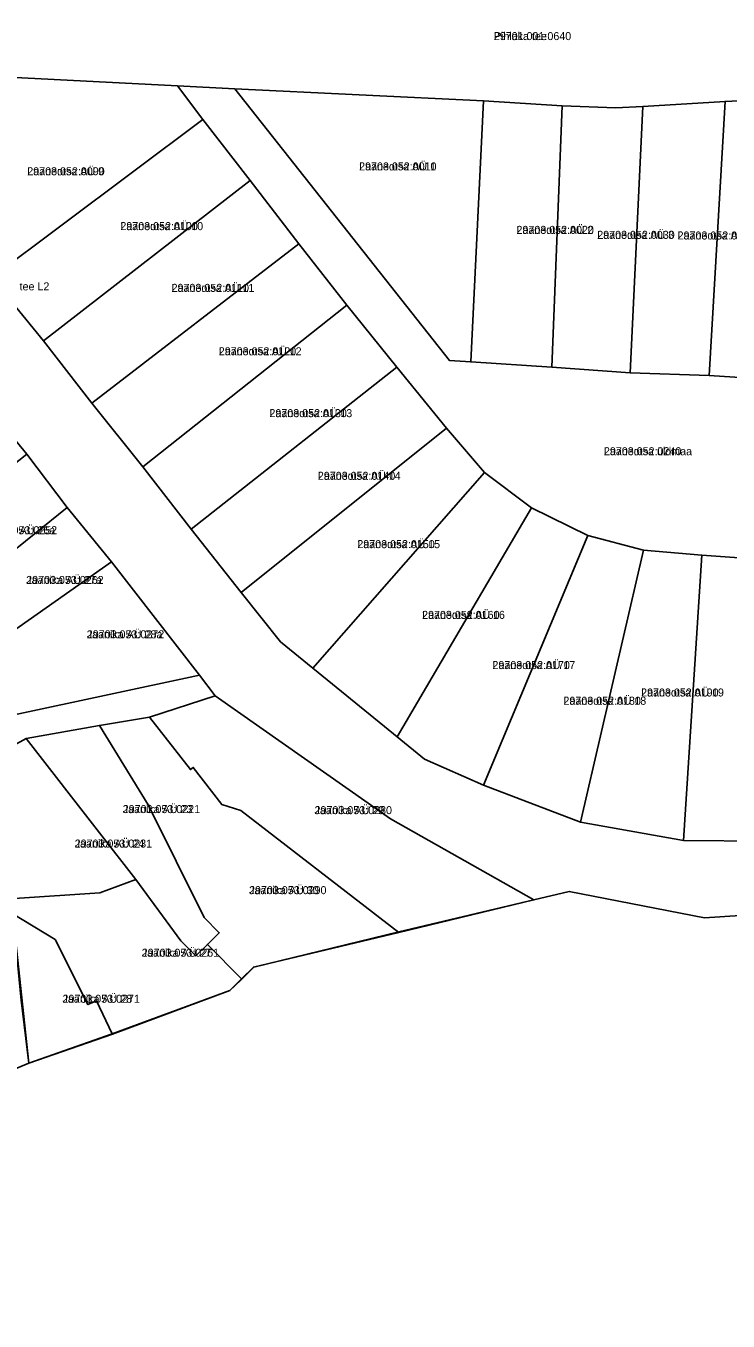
# Model space of a CAD drawing. Extents: x 504287 to 537970, y 6539941 to 6586214.
# Drawn here: x 520134.2 to 520265.8, y 6560331.5 to 6560574.3 of the extents above; entities that cross this region are included whole.
import ezdxf

# ---------------------------------------------------------------- set-up
doc = ezdxf.new("R2010")
doc.units = 0
for name, color, linetype in [('L_AADRESS', 7, 'Continuous'), ('PIIR', 7, 'Continuous'), ('TUNNUS', 7, 'Continuous')]:
    doc.layers.add(name, color=color, linetype=linetype)

msp = doc.modelspace()

# ---------------------------------------------------------------- linework, layer by layer
at = {"layer": 'PIIR'}
for points in [[(520317.67, 6560410.76), (520261.34, 6560407.08), (520236.03, 6560412.01), (520229.4, 6560410.43), (520202.53, 6560425.6), (520169.69, 6560448.66), (520166.73, 6560452.57), (520150.28, 6560473.8), (520141.99, 6560483.98), (520134.38, 6560493.96), (520126.38, 6560503.73), (520118.31, 6560513.94), (520110.33, 6560523.99), (520102.51, 6560533.91), (520094.46, 6560543.92), (520086.59, 6560553.88), (520078.34, 6560564.2), (520070.55, 6560574.23), (520062.55, 6560584.16)], [(520116.2, 6560584.35), (520116.35, 6560565.44), (520115.48, 6560542.75), (520127.8, 6560527.12), (520137.54, 6560515.21), (520146.56, 6560503.53), (520156.13, 6560491.62), (520165.22, 6560479.92), (520174.59, 6560468.07), (520181.93, 6560458.8), (520187.96, 6560453.84), (520203.1, 6560441.57), (520208.92, 6560436.83), (520219.98, 6560431.92), (520238.13, 6560424.99), (520257.44, 6560421.57), (520272.57, 6560421.42)], [(519883.63, 6560513.22), (519926.01, 6560463.67), (519941.07, 6560442.67), (519946.42, 6560436.64), (519971.42, 6560403.04), (519983.27, 6560387.35), (520001.63, 6560363.05), (520022.7, 6560331.46), (520067.9, 6560359.45), (520095.31, 6560364.72), (520109.58, 6560369.9), (520131.77, 6560378.57), (520134.78, 6560379.84), (520150.44, 6560385.26), (520172.45, 6560393.42), (520174.51, 6560395.38), (520176.91, 6560397.82), (520204.12, 6560404.43), (520229.4, 6560410.43), (520236.03, 6560412.01), (520261.34, 6560407.08), (520317.67, 6560410.76)], [(520132.03, 6560445.14), (520166.73, 6560452.57), (520169.69, 6560448.66), (520157.39, 6560444.7), (520148, 6560443.15), (520134.29, 6560440.71), (520131.93, 6560439.39)], [(520131.78, 6560407.84), (520134.78, 6560379.84), (520131.77, 6560378.57)]]:
    msp.add_lwpolyline(points, dxfattribs=at)
for points in [[(520116.2, 6560584.35), (520143.89, 6560583.03), (520172.86, 6560581.52), (520203.54, 6560580.07), (520236.32, 6560578.42), (520254.12, 6560578.76), (520255.84, 6560578.81), (520274.81, 6560579.95), (520296.22, 6560581), (520324.82, 6560582.86), (520329.36, 6560563.63), (520310.39, 6560562.71), (520295.35, 6560561.83), (520280.17, 6560560.87), (520265.21, 6560560.11), (520249.8, 6560559.14), (520244.74, 6560558.9), (520234.71, 6560559.27), (520219.94, 6560560.24), (520173.38, 6560562.51), (520162.65, 6560563.03), (520116.35, 6560565.44)], [(520115.48, 6560542.75), (520116.35, 6560565.44), (520162.65, 6560563.03), (520167.36, 6560556.76), (520127.8, 6560527.12)], [(520173.38, 6560562.51), (520213.57, 6560511.56), (520217.56, 6560511.3), (520232.74, 6560510.31), (520247.42, 6560509.26), (520262.26, 6560508.72), (520277.65, 6560507.71), (520292.44, 6560507.02), (520307.68, 6560506), (520322.39, 6560504.95), (520320.69, 6560471.09), (520275.63, 6560474.01), (520260.84, 6560475.05), (520249.91, 6560475.99), (520239.51, 6560478.77), (520228.96, 6560483.95), (520220.16, 6560490.55), (520213.01, 6560498.89), (520203.71, 6560510.28), (520194.35, 6560521.93), (520185.39, 6560533.44), (520176.22, 6560545.31), (520167.36, 6560556.76), (520162.65, 6560563.03)], [(520219.94, 6560560.24), (520217.56, 6560511.3), (520213.57, 6560511.56), (520173.38, 6560562.51)], [(520219.94, 6560560.24), (520234.71, 6560559.27), (520232.74, 6560510.31), (520217.56, 6560511.3)], [(520247.42, 6560509.26), (520249.8, 6560559.14), (520265.21, 6560560.11), (520262.26, 6560508.72)], [(520262.26, 6560508.72), (520265.21, 6560560.11), (520280.17, 6560560.87), (520277.65, 6560507.71)], [(520232.74, 6560510.31), (520234.71, 6560559.27), (520244.74, 6560558.9), (520249.8, 6560559.14), (520247.42, 6560509.26)], [(520127.8, 6560527.12), (520167.36, 6560556.76), (520176.22, 6560545.31), (520137.54, 6560515.21)], [(520137.54, 6560515.21), (520176.22, 6560545.31), (520185.39, 6560533.44), (520146.56, 6560503.53)], [(520146.56, 6560503.53), (520185.39, 6560533.44), (520194.35, 6560521.93), (520156.13, 6560491.62)], [(520156.13, 6560491.62), (520194.35, 6560521.93), (520203.71, 6560510.28), (520165.22, 6560479.92)], [(520165.22, 6560479.92), (520203.71, 6560510.28), (520213.01, 6560498.89), (520174.59, 6560468.07)], [(520101.35, 6560484.05), (520126.38, 6560503.73), (520134.38, 6560493.96), (520109.15, 6560474.07)], [(520181.93, 6560458.8), (520174.59, 6560468.07), (520213.01, 6560498.89), (520220.16, 6560490.55), (520187.96, 6560453.84)], [(520109.15, 6560474.07), (520134.38, 6560493.96), (520141.99, 6560483.98), (520117.16, 6560464)], [(520203.1, 6560441.57), (520187.96, 6560453.84), (520220.16, 6560490.55), (520228.96, 6560483.95), (520203.78, 6560441.02)], [(520117.16, 6560464), (520141.99, 6560483.98), (520150.28, 6560473.8), (520124.01, 6560455.34)], [(520208.92, 6560436.83), (520203.78, 6560441.02), (520228.96, 6560483.95), (520239.51, 6560478.77), (520219.98, 6560431.92)], [(520238.13, 6560424.99), (520219.98, 6560431.92), (520239.51, 6560478.77), (520249.91, 6560475.99)], [(520257.44, 6560421.57), (520238.13, 6560424.99), (520249.91, 6560475.99), (520260.84, 6560475.05)], [(520272.57, 6560421.42), (520257.44, 6560421.57), (520260.84, 6560475.05), (520275.63, 6560474.01)], [(520124.01, 6560455.34), (520150.28, 6560473.8), (520166.73, 6560452.57), (520132.03, 6560445.14)], [(520169.69, 6560448.66), (520202.53, 6560425.6), (520229.4, 6560410.43), (520204.07, 6560404.34), (520174.49, 6560427.18), (520170.91, 6560428.31), (520165.59, 6560435.27), (520165.05, 6560434.86), (520157.39, 6560444.7)], [(520148, 6560443.15), (520157.14, 6560428.24), (520167.63, 6560407.11), (520170.45, 6560404.28), (520168.25, 6560402.09), (520166.04, 6560399.91), (520163.23, 6560402.74), (520154.81, 6560414.22), (520148.02, 6560423.02), (520134.29, 6560440.71)], [(520174.65, 6560395.64), (520168.25, 6560402.09), (520170.45, 6560404.28), (520167.63, 6560407.11), (520157.14, 6560428.24), (520148, 6560443.15), (520157.39, 6560444.7), (520165.05, 6560434.86), (520165.59, 6560435.27), (520170.91, 6560428.31), (520174.49, 6560427.18), (520204.07, 6560404.34), (520176.85, 6560397.82)], [(520131.93, 6560439.39), (520134.29, 6560440.71), (520148.02, 6560423.02), (520154.81, 6560414.22), (520148.08, 6560411.78), (520132.09, 6560410.71)], [(520147.48, 6560391.5), (520145.84, 6560390.81), (520139.7, 6560402.97), (520131.78, 6560407.84), (520132.09, 6560410.71), (520148.08, 6560411.78), (520154.81, 6560414.22), (520163.23, 6560402.74), (520166.04, 6560399.91), (520168.25, 6560402.09), (520174.65, 6560395.64), (520172.45, 6560393.46), (520150.39, 6560385.33)], [(520133.32, 6560391.61), (520131.78, 6560407.84), (520139.7, 6560402.97), (520145.84, 6560390.81), (520147.48, 6560391.5), (520150.39, 6560385.33), (520134.78, 6560379.84)]]:
    msp.add_lwpolyline(points, close=True, dxfattribs=at)

# ---------------------------------------------------------------- texts
at = {"layer": 'L_AADRESS'}
for s, p in [('Pihlaka tee', (520221.89, 6560571.62)), ('Laaneotsa AÜ 9', (520134.49, 6560546.28)), ('Laaneotsa AÜ 1', (520196.66, 6560547.19)), ('Laaneotsa AÜ 10', (520151.93, 6560535.99)), ('Laaneotsa AÜ 2', (520226.14, 6560535.29)), ('Laaneotsa AÜ 3', (520241.27, 6560534.36)), ('Laaneotsa AÜ 4', (520256.32, 6560534.24)), ('Pundi-Jaanika tee L2', (520119.78, 6560524.7)), ('Laaneotsa AÜ 11', (520161.53, 6560524.42)), ('Laaneotsa AÜ 12', (520170.37, 6560512.53)), ('Laaneotsa AÜ 13', (520179.86, 6560500.93)), ('Laaneotsa üldmaa', (520242.52, 6560493.79)), ('Laaneotsa AÜ 14', (520188.93, 6560489.18)), ('Jaanika AÜ 26a', (520125.58, 6560478.98)), ('Laaneotsa AÜ 15', (520196.32, 6560476.37)), ('Jaanika AÜ 27a', (520134.29, 6560469.66)), ('Laaneotsa AÜ 16', (520208.46, 6560463.11)), ('Jaanika AÜ 28a', (520145.64, 6560459.47)), ('Laaneotsa AÜ 17', (520221.64, 6560453.7)), ('Laaneotsa AÜ 19', (520249.49, 6560448.56)), ('Laaneotsa AÜ 18', (520234.94, 6560447.01)), ('Jaanika AÜ 23', (520152.37, 6560426.7)), ('Jaanika AÜ 29', (520188.31, 6560426.5)), ('Jaanika AÜ 24', (520143.37, 6560420.24)), ('Jaanika AÜ 30', (520176.04, 6560411.5)), ('Jaanika AÜ 27', (520155.93, 6560399.77)), ('Jaanika AÜ 28', (520141.09, 6560391.14))]:
    msp.add_text(s, height=1.5, dxfattribs=at).set_placement(p)
at = {"layer": 'TUNNUS'}
for s, p in [('29701:001:0640', (520221.89, 6560571.62)), ('29703:052:0090', (520134.49, 6560546.28)), ('29703:052:0010', (520196.66, 6560547.19)), ('29703:052:0100', (520151.93, 6560535.99)), ('29703:052:0020', (520226.14, 6560535.29)), ('29703:052:0030', (520241.27, 6560534.36)), ('29703:052:0040', (520256.32, 6560534.24)), ('29703:052:0110', (520161.53, 6560524.42)), ('29703:052:0120', (520170.37, 6560512.53)), ('29703:052:0130', (520179.86, 6560500.93)), ('29703:052:0240', (520242.52, 6560493.79)), ('29703:052:0140', (520188.93, 6560489.18)), ('29703:053:0252', (520125.58, 6560478.98)), ('29703:052:0150', (520196.32, 6560476.37)), ('29703:053:0262', (520134.29, 6560469.66)), ('29703:052:0160', (520208.46, 6560463.11)), ('29703:053:0272', (520145.64, 6560459.47)), ('29703:052:0170', (520221.64, 6560453.7)), ('29703:052:0190', (520249.49, 6560448.56)), ('29703:052:0180', (520234.94, 6560447.01)), ('29703:053:0221', (520152.37, 6560426.7)), ('29703:053:0280', (520188.31, 6560426.5)), ('29703:053:0231', (520143.37, 6560420.24)), ('29703:053:0290', (520176.04, 6560411.5)), ('29703:053:0261', (520155.93, 6560399.77)), ('29703:053:0271', (520141.09, 6560391.14))]:
    msp.add_text(s, height=1.5, dxfattribs=at).set_placement(p)

doc.saveas('drawing.dxf')
